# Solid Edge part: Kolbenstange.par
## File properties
Username: ahadarics
Dokumentum tartalom típus: 0
Author: ahadarics
Last saved by: ahadarics
Revision: 80
Sűrűség: 0,000 kg/m^3
Pontosság: 0,990
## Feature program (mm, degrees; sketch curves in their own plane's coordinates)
base feature "unnamed BaseFeature 1"
thread "unnamed Thread 1"
chamfer "unnamed Chamfer 1"
sketch for "Kihúzás_1" plane through (63.5, 0, 0) normal (1, 0, 0) x-axis (0, -0.866025, -0.5)
  circle centre (0, 0) radius 12.5
extrude "Kihúzás_1" add finite 33 along -normal
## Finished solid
Body 1: solid body, 18 faces, 34 edges, 18 vertices.
  Faces by surface: plane 9, cone 7, cylinder 2
  Edges by curve: line 12, spline 12, circle 10
Bounding box of the edges (mm): 200.500 x 25.000 x 25.000, from (-137, -12.5, -12.5) to (63.5, 12.5, 12.5).
Cylindrical faces by radius (mm): R5 x1, R12.5 x1
Conical faces (half-angle, radius in mm at the cone's reference point): 30 deg R6.25 x6, 45 deg R4.3 x1
Planar faces by outward normal: +x 1, +y 1, -x 2, -y 1, oblique 4
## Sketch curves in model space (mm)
circle centre (63.5, 0, 0) radius 12.5
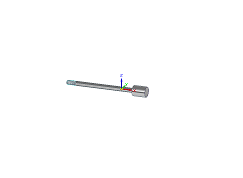
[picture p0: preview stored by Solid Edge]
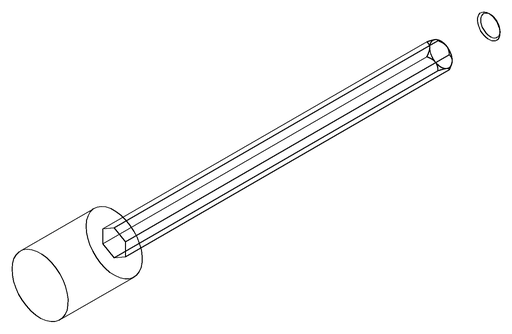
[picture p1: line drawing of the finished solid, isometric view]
